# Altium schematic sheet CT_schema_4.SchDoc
size 578 x 363 mm
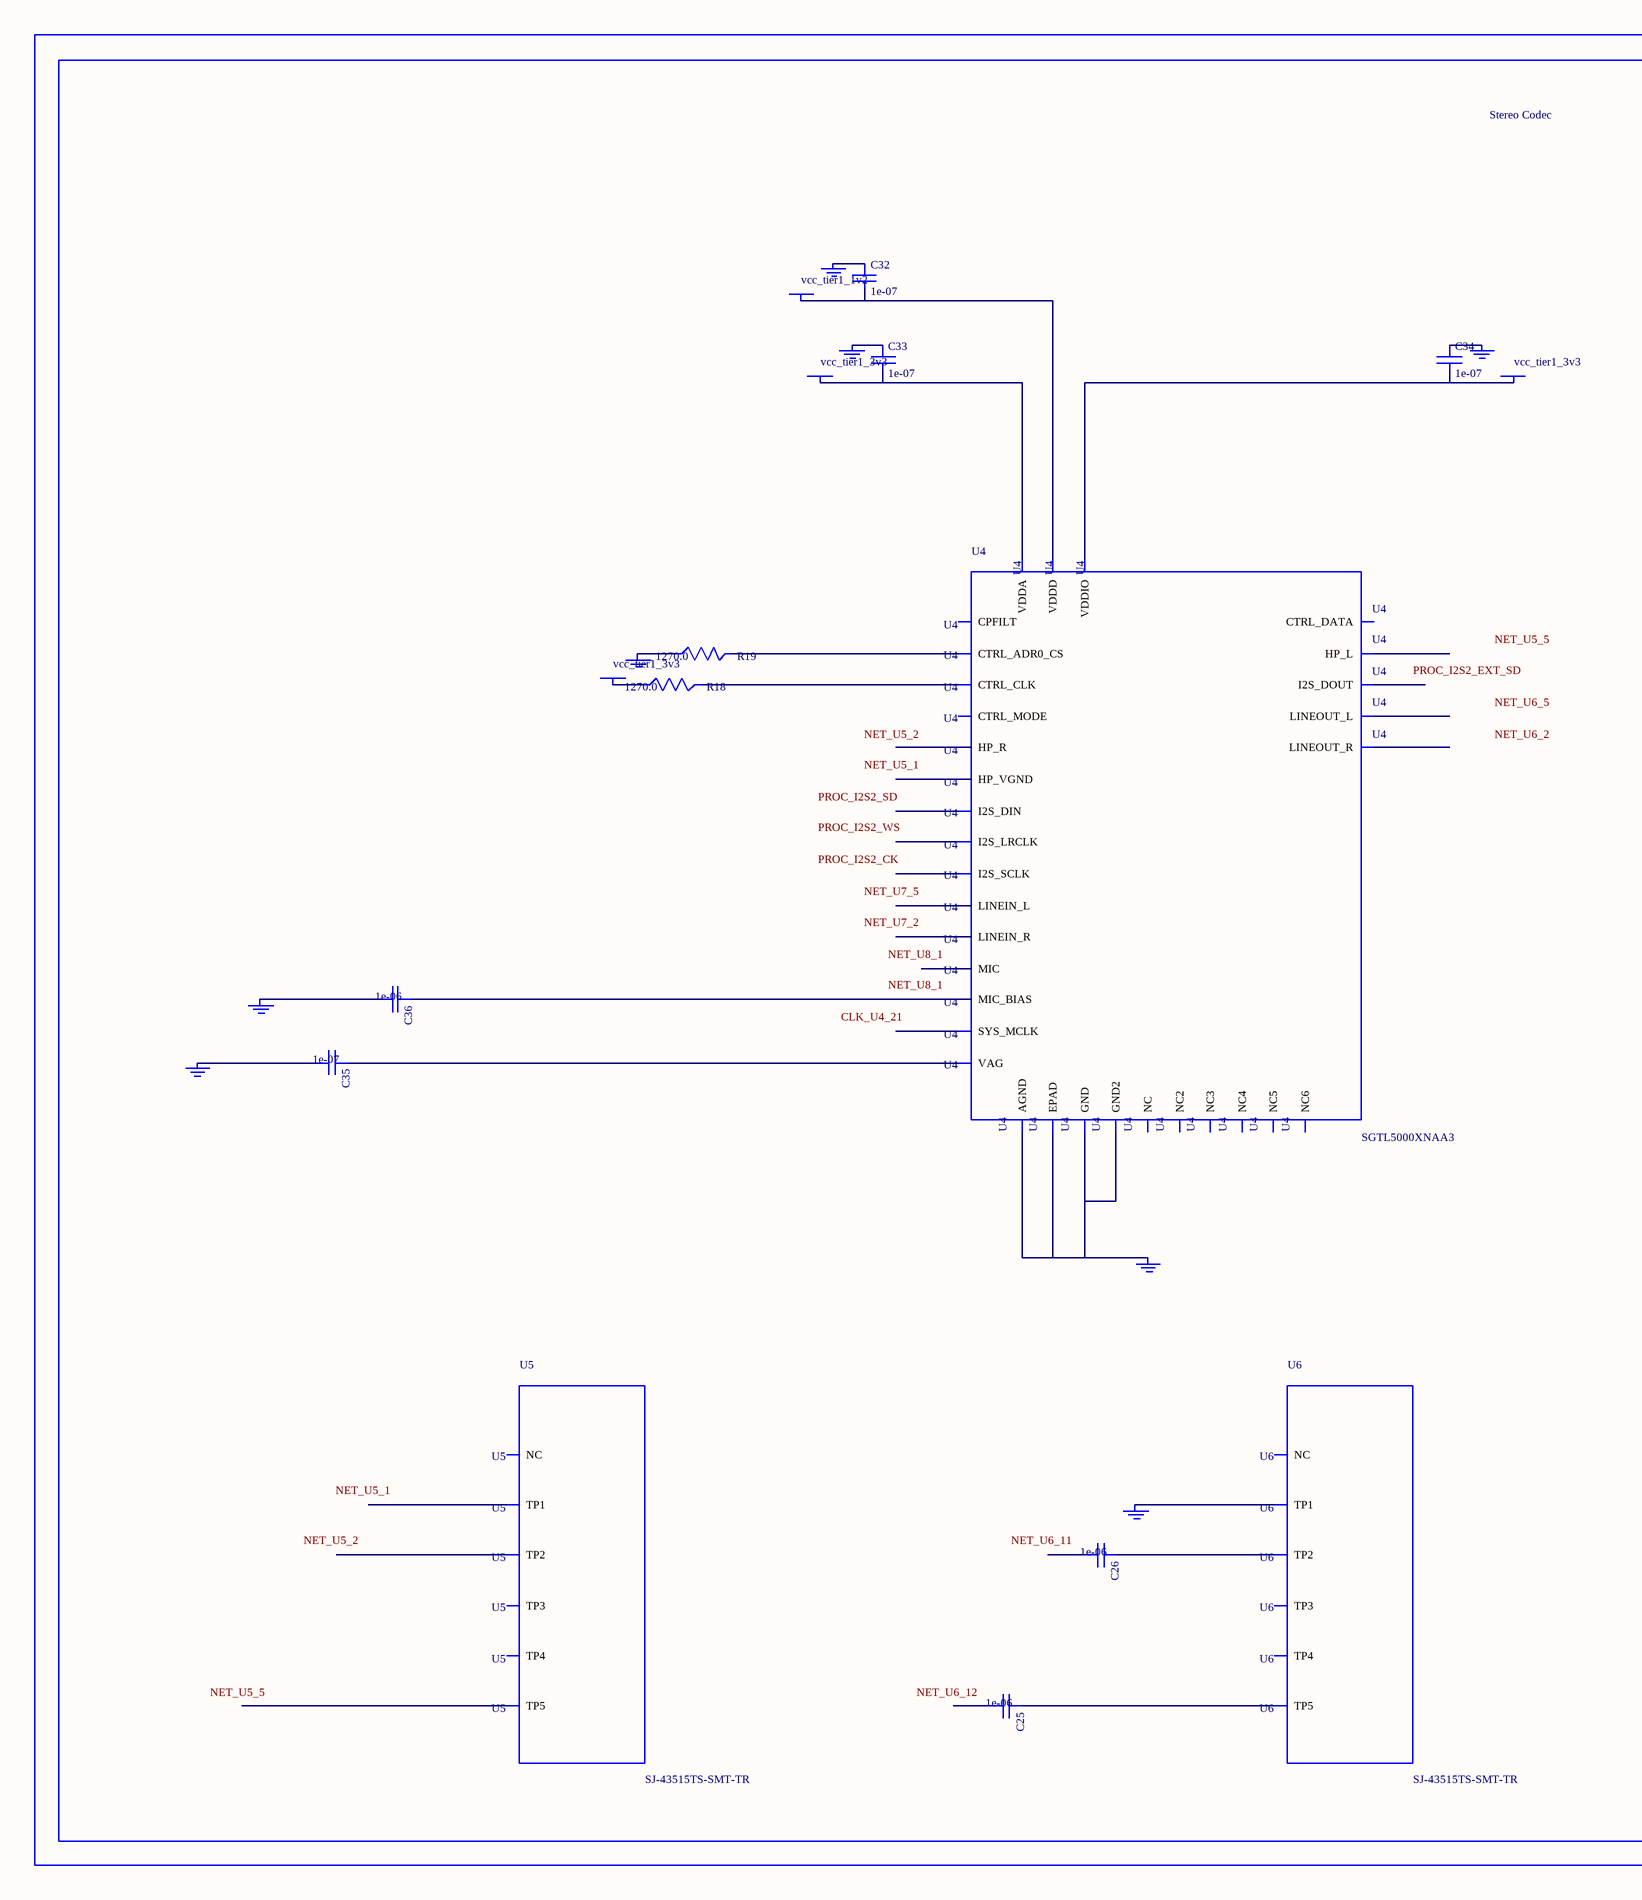
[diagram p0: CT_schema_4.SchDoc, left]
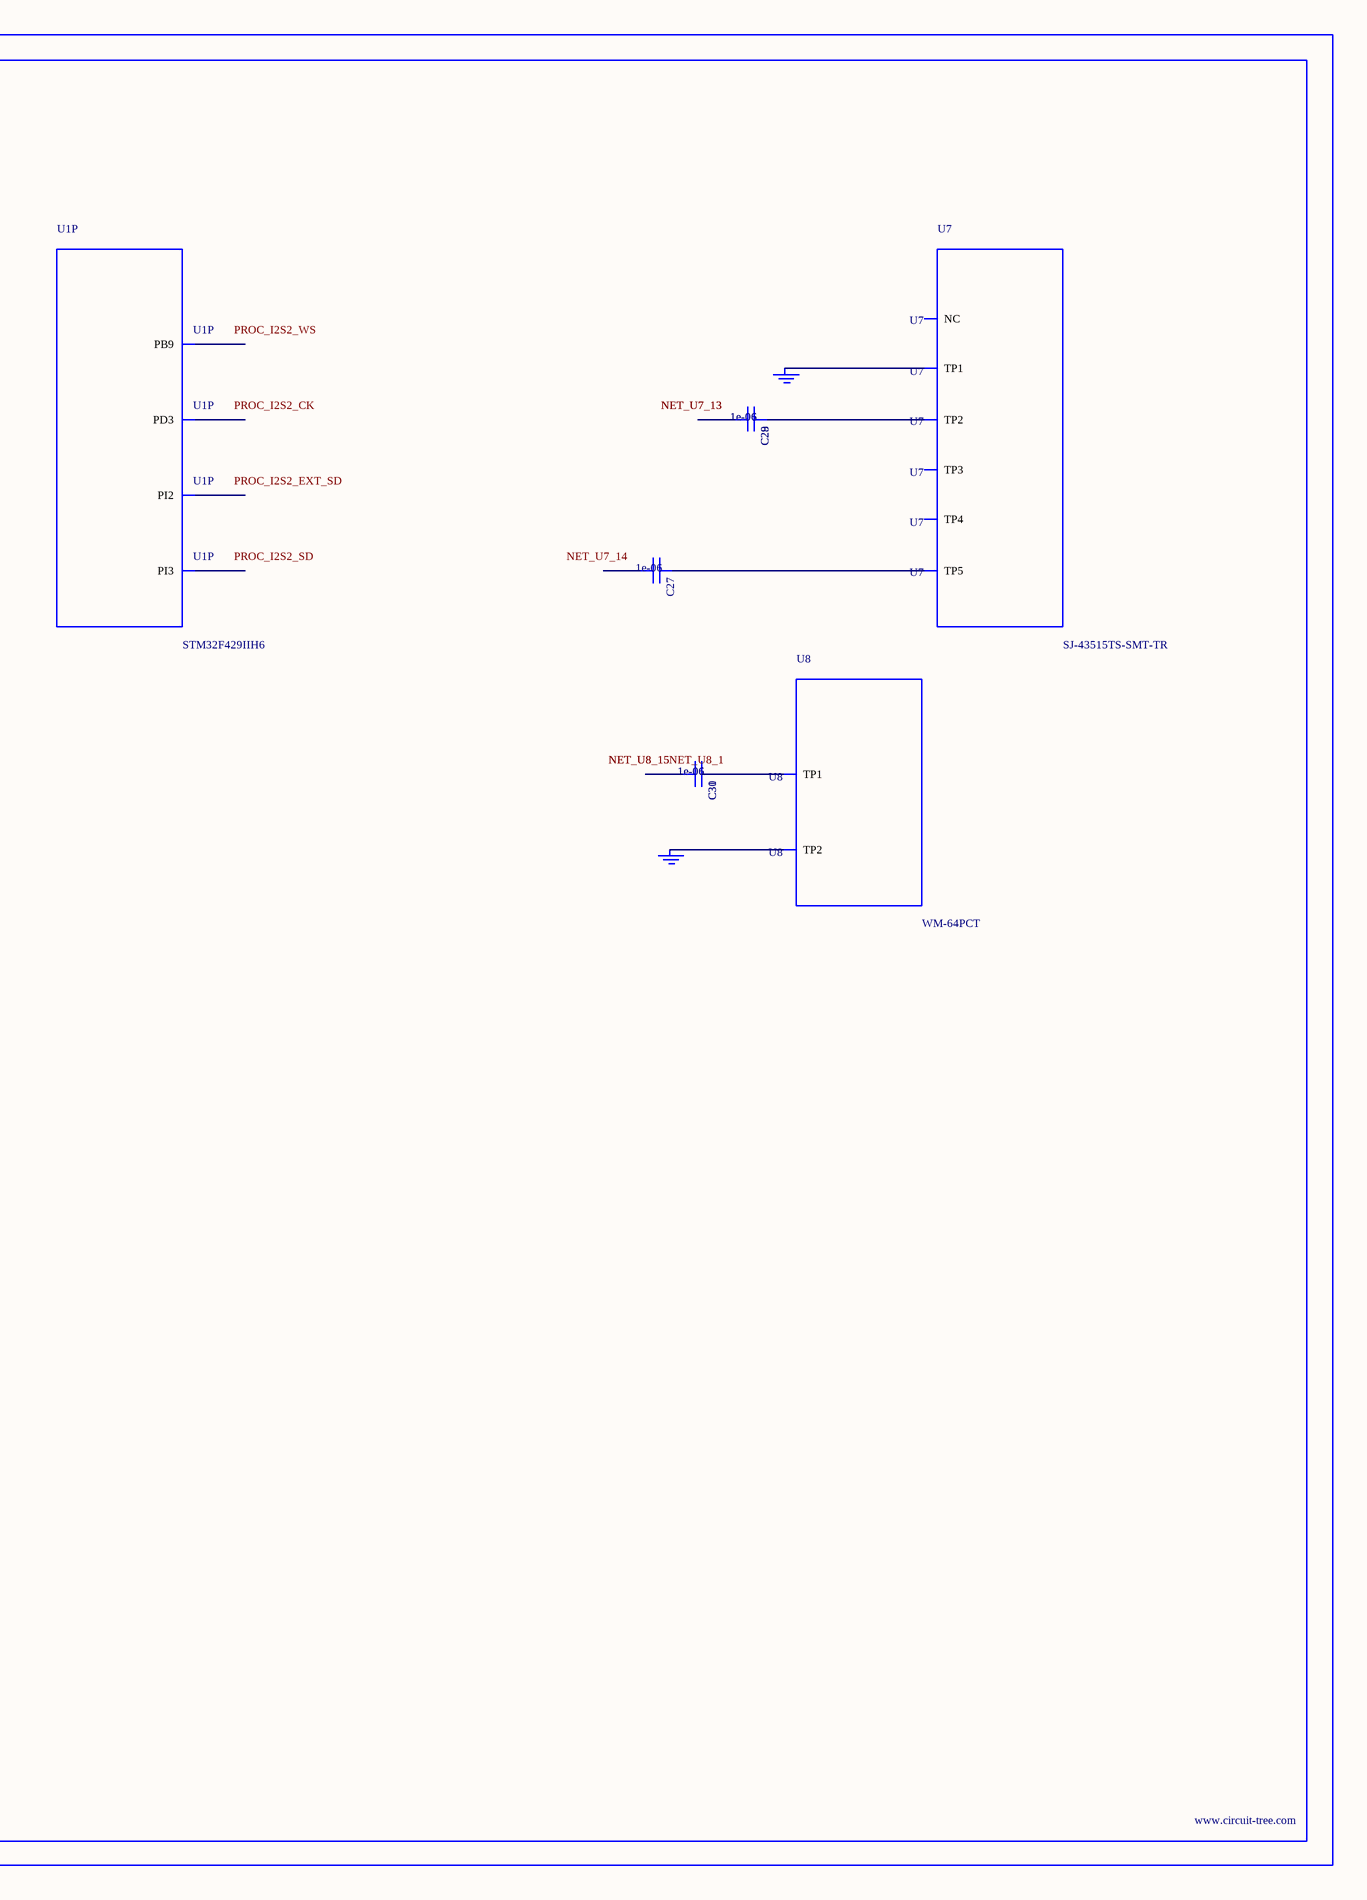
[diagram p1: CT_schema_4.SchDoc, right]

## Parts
BORDER3  (no value)
C25  1e-06  [C0603]
C26  1e-06  [C0603]
C27  1e-06  [C0603]
C28  1e-06  [C0603]
C29  1e-06  [C0603]
C30  1e-06  [C0603]
C31  1e-06  [C0603]
C32  1e-07  [C0402]
C33  1e-07  [C0402]
C34  1e-07  [C0402]
C35  1e-07  [C0402]
C36  1e-06  [C0603]
GND_INSTANCE_3_0  (no value)
GND_INSTANCE_3_1  (no value)
GND_INSTANCE_3_2  (no value)
GND_INSTANCE_3_3  (no value)
GND_INSTANCE_3_4  (no value)
GND_INSTANCE_3_5  (no value)
GND_INSTANCE_3_6  (no value)
GND_INSTANCE_3_7  (no value)
GND_INSTANCE_3_8  (no value)
GND_INSTANCE_3_9  (no value)
GND_INSTANCE_3_10  (no value)
POWER_INSTANCE_3_0  vcc_tier1_3v3
POWER_INSTANCE_3_1  vcc_tier1_3v3
POWER_INSTANCE_3_2  vcc_tier1_3v3
POWER_INSTANCE_3_3  vcc_tier1_1v2
R18  1270.0  [R0603]
R19  1270.0  [R0603]
U1  STM32F429IIH6  [UFBGA176_25]  (part P of 16)
U4  SGTL5000XNAA3  [QFN-32]
U5  SJ-43515TS-SMT-TR  [SJ-43515TS-SMT-TR]
U6  SJ-43515TS-SMT-TR  [SJ-43515TS-SMT-TR]
U7  SJ-43515TS-SMT-TR  [SJ-43515TS-SMT-TR]
U8  WM-64PCT  [WM-64PC]

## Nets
NetC25_1: C25.1 U6.5(TP5)
NetC26_1: C26.1 U6.2(TP2)
NetC27_1: C27.1 U7.5(TP5)
NetC28_1: C28.1 C29.1 U7.2(TP2)
NetC28_2: C28.2 C29.2
NetC30_1: C30.1 C31.1 U8.1(TP1)
NetC30_2: C30.2 C31.2
NetC32_1: C32.1 GND_INSTANCE_3_5.0(GND)
NetC32_2: C32.2 POWER_INSTANCE_3_3.0(PWR) U4.30(VDDD)
NetC33_1: C33.1 GND_INSTANCE_3_1.0(GND)
NetC33_2: C33.2 POWER_INSTANCE_3_0.0(PWR) U4.5(VDDA)
NetC34_1: C34.1 GND_INSTANCE_3_4.0(GND)
NetC34_2: C34.2 POWER_INSTANCE_3_1.0(PWR) U4.20(VDDIO)
NetC35_1: C35.1 U4.10(VAG)
NetC35_2: C35.2 GND_INSTANCE_3_2.0(GND)
NetC36_1: C36.1 U4.16(MIC_BIAS)
NetC36_2: C36.2 GND_INSTANCE_3_3.0(GND)
NetGND_INSTANCE_3_0_0: GND_INSTANCE_3_0.0(GND) U4.1(GND) U4.3(GND2) U4.7(AGND) U4.EXP(EPAD)
NetGND_INSTANCE_3_6_0: GND_INSTANCE_3_6.0(GND) R19.1
NetGND_INSTANCE_3_7_0: GND_INSTANCE_3_7.0(GND) U6.1(TP1)
NetGND_INSTANCE_3_8_0: GND_INSTANCE_3_8.0(GND) GND_INSTANCE_3_9.0(GND) U7.1(TP1)
NetGND_INSTANCE_3_10_0: GND_INSTANCE_3_10.0(GND) U8.2(TP2)
NetPOWER_INSTANCE_3_2_0: POWER_INSTANCE_3_2.0(PWR) R18.1
NetR18_2: R18.2 U4.29(CTRL_CLK)
NetR19_2: R19.2 U4.31(CTRL_ADR0_CS)

Not connected (* = marked no-connect by the designer): C25 2; C26 2; C27 2; U1 B4(PB9) C13(PI3) C14(PI2) D11(PD3); U4 2(HP_R) 4(HP_VGND) 6(HP_L) 8(NC) 9(NC2) 11(LINEOUT_R) 12(LINEOUT_L) 13(LINEIN_R) 14(LINEIN_L) 15(MIC) 17(NC3) 18(CPFILT) 19(NC4) 21(SYS_MCLK) 22(NC5) 23(I2S_LRCLK) 24(I2S_SCLK) 25(I2S_DOUT) 26(I2S_DIN) 27(CTRL_DATA) 28(NC6) 32(CTRL_MODE); U5 1(TP1) 2(TP2) 3(TP3) 4(TP4) 5(TP5) 6(NC); U6 3(TP3) 4(TP4) 6(NC); U7 3(TP3) 4(TP4) 6(NC)

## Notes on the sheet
- Labels drawn without touching a wire or pin: CLK_U4_21, NET_U5_1, NET_U5_2, NET_U5_5, NET_U6_2, NET_U6_5, NET_U6_11, NET_U6_12, NET_U7_2, NET_U7_5, NET_U7_14, NET_U8_1, PROC_I2S2_CK, PROC_I2S2_EXT_SD, PROC_I2S2_SD, PROC_I2S2_WS

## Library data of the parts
BORDER3 = BORDER_PAGE3
C25-C31 C36 = C0603C105K3RACTU
C32-C35 = C0402C104K3RACTU
GND_INSTANCE_3_0-GND_INSTANCE_3_10 = GND
POWER_INSTANCE_3_0-POWER_INSTANCE_3_3 = PWR
R18 R19 = RC0603FR-071K27L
